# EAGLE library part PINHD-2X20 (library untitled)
PIN HEADER
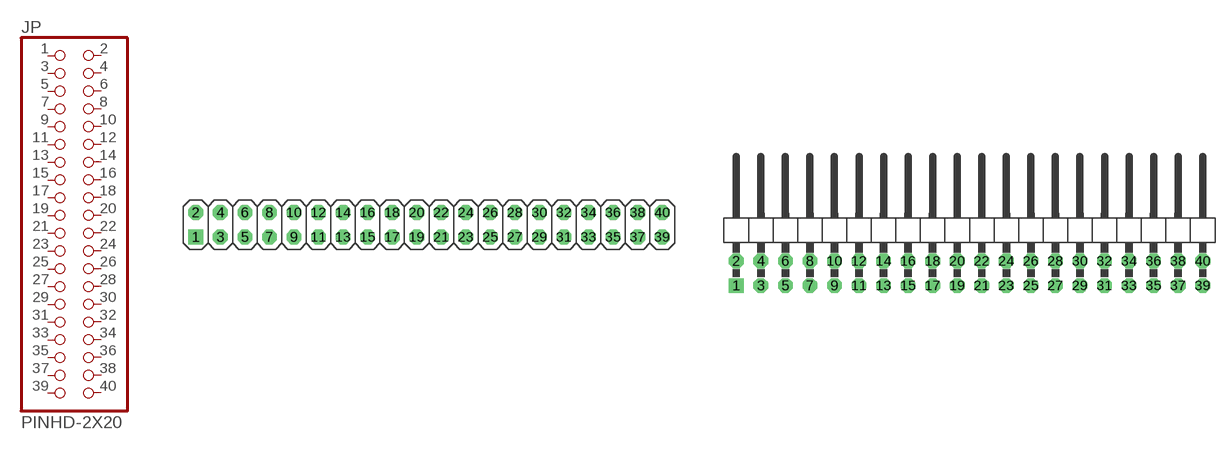
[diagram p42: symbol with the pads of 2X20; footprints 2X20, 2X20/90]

Designator prefix JP

## PINHD-2X20_2.54  [2X20]
1  1  pas
2  2  pas
3  3  pas
4  4  pas
5  5  pas
6  6  pas
7  7  pas
8  8  pas
9  9  pas
10  10  pas
11  11  pas
12  12  pas
13  13  pas
14  14  pas
15  15  pas
16  16  pas
17  17  pas
18  18  pas
19  19  pas
20  20  pas
21  21  pas
22  22  pas
23  23  pas
24  24  pas
25  25  pas
26  26  pas
27  27  pas
28  28  pas
29  29  pas
30  30  pas
31  31  pas
32  32  pas
33  33  pas
34  34  pas
35  35  pas
36  36  pas
37  37  pas
38  38  pas
39  39  pas
40  40  pas

## PINHD-2X20_2.54-90°  [2X20/90]
Pads as for 2X20

## PINHD-2X20_2.00  [2X20M]
Pads as for 2X20

## PINHD-2X20_2.54-SMD  [2X20SMD]
Pads as for 2X20

## PINHD-2X20_2.54-SMD-90°  [2X20SMD/90]
Pads as for 2X20

## Footprint 2X20 (pad centres in mm)
PIN HEADER - 2.54
drill 1.016 square: 1 -24.13,-1.27
drill 1.016 octagon: 2 -24.13,1.27; 3 -21.59,-1.27; 4 -21.59,1.27; 5 -19.05,-1.27; 6 -19.05,1.27; 7 -16.51,-1.27; 8 -16.51,1.27; 9 -13.97,-1.27; 10 -13.97,1.27; 11 -11.43,-1.27; 12 -11.43,1.27; 13 -8.89,-1.27; 14 -8.89,1.27; 15 -6.35,-1.27; 16 -6.35,1.27; 17 -3.81,-1.27; 18 -3.81,1.27; 19 -1.27,-1.27; 20 -1.27,1.27; 21 1.27,-1.27; 22 1.27,1.27; 23 3.81,-1.27; 24 3.81,1.27; 25 6.35,-1.27; 26 6.35,1.27; 27 8.89,-1.27; 28 8.89,1.27; 29 11.43,-1.27; 30 11.43,1.27; 31 13.97,-1.27; 32 13.97,1.27; 33 16.51,-1.27; 34 16.51,1.27; 35 19.05,-1.27; 36 19.05,1.27; 37 21.59,-1.27; 38 21.59,1.27; 39 24.13,-1.27; 40 24.13,1.27

## Footprint 2X20/90 (pad centres in mm)
PIN HEADER - 2.54 90°
drill 1.016 square: 1 -24.13,-6.35
drill 1.016 octagon: 2 -24.13,-3.81; 3 -21.59,-6.35; 4 -21.59,-3.81; 5 -19.05,-6.35; 6 -19.05,-3.81; 7 -16.51,-6.35; 8 -16.51,-3.81; 9 -13.97,-6.35; 10 -13.97,-3.81; 11 -11.43,-6.35; 12 -11.43,-3.81; 13 -8.89,-6.35; 14 -8.89,-3.81; 15 -6.35,-6.35; 16 -6.35,-3.81; 17 -3.81,-6.35; 18 -3.81,-3.81; 19 -1.27,-6.35; 20 -1.27,-3.81; 21 1.27,-6.35; 22 1.27,-3.81; 23 3.81,-6.35; 24 3.81,-3.81; 25 6.35,-6.35; 26 6.35,-3.81; 27 8.89,-6.35; 28 8.89,-3.81; 29 11.43,-6.35; 30 11.43,-3.81; 31 13.97,-6.35; 32 13.97,-3.81; 33 16.51,-6.35; 34 16.51,-3.81; 35 19.05,-6.35; 36 19.05,-3.81; 37 21.59,-6.35; 38 21.59,-3.81; 39 24.13,-6.35; 40 24.13,-3.81

## Footprint 2X20M (pad centres in mm)
PIN HEADER - 2
drill 0.914 square: 1 -19,-1
drill 0.914 round: 2 -19,1; 3 -17,-1; 4 -17,1; 5 -15,-1; 6 -15,1; 7 -13,-1; 8 -13,1; 9 -11,-1; 10 -11,1; 11 -9,-1; 12 -9,1; 13 -7,-1; 14 -7,1; 15 -5,-1; 16 -5,1; 17 -3,-1; 18 -3,1; 19 -1,-1; 20 -1,1; 21 1,-1; 22 1,1; 23 3,-1; 24 3,1; 25 5,-1; 26 5,1; 27 7,-1; 28 7,1; 29 9,-1; 30 9,1; 31 11,-1; 32 11,1; 33 13,-1; 34 13,1; 35 15,-1; 36 15,1; 37 17,-1; 38 17,1; 39 19,-1; 40 19,1

## Footprint 2X20SMD (pad centres in mm)
PIN HEADER - 2.54 SMD
smd 1.016 x 3.302: 1 -1.27,-3.81; 2 -1.27,1.27; 3 1.27,-3.81; 4 1.27,1.27; 5 3.81,-3.81; 6 3.81,1.27; 7 6.35,-3.81; 8 6.35,1.27; 9 8.89,-3.81; 10 8.89,1.27; 11 11.43,-3.81; 12 11.43,1.27; 13 13.97,-3.81; 14 13.97,1.27; 15 16.51,-3.81; 16 16.51,1.27; 17 19.05,-3.81; 18 19.05,1.27; 19 21.59,-3.81; 20 21.59,1.27; 21 24.13,-3.81; 22 24.13,1.27; 23 26.67,-3.81; 24 26.67,1.27; 25 29.21,-3.81; 26 29.21,1.27; 27 31.75,-3.81; 28 31.75,1.27; 29 34.29,-3.81; 30 34.29,1.27; 31 36.83,-3.81; 32 36.83,1.27; 33 39.37,-3.81; 34 39.37,1.27; 35 41.91,-3.81; 36 41.91,1.27; 37 44.45,-3.81; 38 44.45,1.27; 39 46.99,-3.81; 40 46.99,1.27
